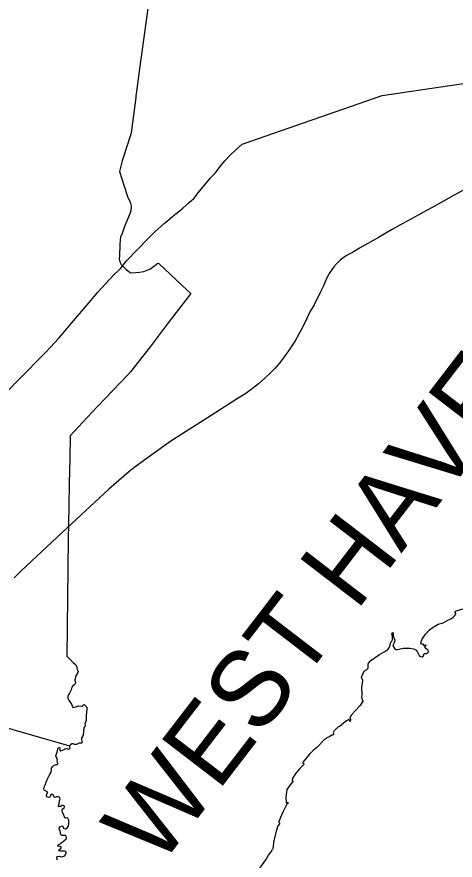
# Model space of a CAD drawing. Extents: x 0 to 2603, y -226 to 830.
# Drawn here: x 148.13 to 155.87, y 515.3 to 530.19 of the extents above; entities that cross this region are included whole.
import ezdxf

# ---------------------------------------------------------------- set-up
doc = ezdxf.new("R2010")
doc.units = 0
for name, color, linetype in [('CT_TSH_Map_Interstate_Roads', 7, 'Continuous'), ('CT_TSH_Map_Town_Limits', 7, 'Continuous'), ('CT_TSH_Map_Town_Text', 7, 'Continuous'), ('CT_TSH_Map_US_and_State_Routes', 7, 'Continuous')]:
    doc.layers.add(name, color=color, linetype=linetype)

msp = doc.modelspace()

# ---------------------------------------------------------------- linework, layer by layer
at = {"layer": 'CT_TSH_Map_Interstate_Roads'}
for p, q in [((155.849, 527.039), (155.475, 526.831)), ((155.217, 526.69), (155.022, 526.579)), ((154.747, 526.427), (154.512, 526.293)), ((154.512, 526.293), (154.182, 526.104)), ((153.724, 525.773), (153.657, 525.678)), ((153.657, 525.678), (153.605, 525.583)), ((149.753, 521.846), (149.506, 521.621)), ((148.66, 520.83), (148.482, 520.664)), ((148.482, 520.664), (148.199, 520.4)), ((148.199, 520.4), (148.081, 520.285))]:
    msp.add_line(p, q, dxfattribs=at)
for points in [[(156.789, 527.553), (156.703, 527.508), (156.56, 527.428), (156.136, 527.195), (155.849, 527.039)], [(155.475, 526.831), (155.364, 526.768), (155.217, 526.69)], [(155.022, 526.579), (154.889, 526.51), (154.747, 526.427)], [(154.182, 526.104), (154.056, 526.031), (153.983, 525.996), (153.931, 525.963), (153.838, 525.891), (153.781, 525.836), (153.724, 525.773)], [(153.605, 525.583), (153.545, 525.44), (153.487, 525.32)], [(153.487, 525.32), (153.422, 525.187), (153.39, 525.134)], [(153.39, 525.134), (153.376, 525.104), (153.298, 524.968), (153.249, 524.863), (153.18, 524.716), (153.079, 524.534)], [(153.079, 524.534), (153.041, 524.468), (152.926, 524.292), (152.85, 524.185)], [(152.85, 524.185), (152.765, 524.073), (152.683, 523.982), (152.603, 523.899), (152.515, 523.813), (152.394, 523.708)], [(152.394, 523.708), (152.261, 523.603), (152.154, 523.529), (152.035, 523.453), (151.561, 523.152), (150.848, 522.696), (150.495, 522.442)], [(150.495, 522.442), (150.194, 522.228), (150.104, 522.152), (149.753, 521.846)], [(149.506, 521.621), (149.096, 521.238), (148.66, 520.83)]]:
    msp.add_lwpolyline(points, dxfattribs=at)
at = {"layer": 'CT_TSH_Map_Town_Limits'}
for points in [[(150.486, 530.685), (150.296, 529.272), (150.233, 528.83), (150.23, 528.794), (150.23, 528.765), (150.15, 528.144), (150.132, 528.083), (150.014, 527.721), (149.988, 527.648), (149.942, 527.461), (150.022, 527.198), (150.08, 527.018), (150.13, 526.917), (150.15, 526.849), (150.143, 526.765), (150.125, 526.713), (150.028, 526.485), (149.987, 526.365), (149.96, 526.297), (149.952, 526.251), (149.949, 526.17), (149.942, 525.961), (149.938, 525.915), (149.946, 525.863), (149.971, 525.817), (150.057, 525.727), (150.131, 525.677), (150.162, 525.668), (150.297, 525.68), (150.372, 525.695), (150.489, 525.742), (150.619, 525.839), (150.633, 525.837), (151.047, 525.445), (151.2, 525.307), (150.802, 524.789), (150.481, 524.363), (150.135, 523.919), (150.086, 523.87), (149.554, 523.31), (149.289, 523.024), (149.071, 522.793), (149.064, 522.39), (149.05, 521.956), (149.045, 521.542), (149.036, 520.957), (149.009, 518.902), (149.122, 518.788), (149.172, 518.749), (149.185, 518.723), (149.195, 518.666), (149.214, 518.63), (149.205, 518.608), (149.166, 518.543), (149.164, 518.536), (149.158, 518.505), (149.15, 518.474), (149.166, 518.436), (149.163, 518.42), (149.15, 518.399), (149.126, 518.379), (149.102, 518.353), (149.088, 518.307), (149.057, 518.246), (149.038, 518.216), (149.03, 518.191), (149.031, 518.159), (149.053, 518.109), (149.096, 518.052), (149.117, 517.994), (149.171, 518.004), (149.226, 518.021), (149.274, 518.014), (149.295, 518.028), (149.312, 518.044), (149.324, 518.039), (149.349, 518.014), (149.364, 517.996), (149.367, 517.961), (149.354, 517.852), (149.352, 517.764), (149.331, 517.705), (149.334, 517.682), (149.342, 517.669), (149.318, 517.643), (149.312, 517.625), (149.299, 517.506), (149.269, 517.455), (149.273, 517.421), (149.283, 517.374), (149.274, 517.364), (149.261, 517.36), (149.224, 517.362), (149.181, 517.34), (149.149, 517.338), (149.121, 517.349), (149.1, 517.352), (149.078, 517.332)], [(155.509, 519.428), (155.57, 519.466), (155.656, 519.488), (155.74, 519.536), (155.79, 519.558), (155.832, 519.588), (155.861, 519.617)], [(155.861, 519.617), (155.878, 519.642), (155.87, 519.674), (155.88, 519.692), (155.923, 519.714), (156.053, 519.748), (156.101, 519.752)], [(154.746, 519.301), (154.77, 519.318)], [(154.77, 519.318), (154.772, 519.309), (154.776, 519.269), (154.787, 519.224), (154.802, 519.182), (154.796, 519.154), (154.765, 519.079)], [(155.266, 519.113), (155.261, 519.137), (155.288, 519.2), (155.344, 519.286), (155.415, 519.365), (155.477, 519.411), (155.509, 519.428)], [(154.746, 519.301), (154.754, 519.257), (154.758, 519.204), (154.751, 519.167)], [(154.457, 518.878), (154.53, 518.93), (154.616, 518.975), (154.686, 519.023)], [(154.686, 519.023), (154.711, 519.057), (154.728, 519.122)], [(154.751, 519.167), (154.728, 519.14), (154.723, 519.119)], [(154.817, 519.02), (154.771, 519.082)], [(154.817, 519.02), (154.846, 519.017), (154.952, 519.041), (155.068, 519.042), (155.139, 519.027), (155.18, 519.006), (155.199, 518.979), (155.234, 518.912), (155.258, 518.896), (155.288, 518.89), (155.31, 518.904), (155.31, 518.912)], [(155.272, 519.115), (155.291, 519.115), (155.314, 519.086), (155.345, 519.101), (155.355, 519.085), (155.327, 519.065), (155.338, 519.049)], [(155.31, 518.912), (155.322, 518.944), (155.365, 518.944), (155.387, 518.957), (155.396, 518.979), (155.39, 519.003), (155.374, 519.019), (155.359, 519.029)], [(155.338, 519.049), (155.359, 519.029)], [(154.418, 518.851), (154.457, 518.878)], [(154.215, 518.523), (154.231, 518.574), (154.266, 518.64), (154.319, 518.676), (154.33, 518.685), (154.335, 518.712), (154.331, 518.734), (154.33, 518.759), (154.336, 518.776)], [(154.336, 518.776), (154.374, 518.817), (154.394, 518.835), (154.418, 518.851)], [(154.226, 518.275), (154.221, 518.288), (154.218, 518.347), (154.238, 518.469), (154.215, 518.523)], [(154.176, 518.01), (154.182, 518.021), (154.203, 518.038), (154.239, 518.092), (154.248, 518.098), (154.235, 518.111), (154.225, 518.144), (154.221, 518.183), (154.228, 518.225), (154.226, 518.275)], [(154.035, 517.852), (154.041, 517.867), (154.176, 518.01)], [(154.022, 517.746), (154.026, 517.781), (154.013, 517.812), (154.019, 517.83), (154.03, 517.85), (154.035, 517.852)], [(147.746, 517.692), (149.06, 517.313)], [(153.801, 517.651), (153.827, 517.663), (153.865, 517.694)], [(153.988, 517.78), (153.952, 517.758), (153.865, 517.694)], [(154.022, 517.746), (153.988, 517.78)], [(153.582, 517.442), (153.611, 517.464), (153.647, 517.48), (153.685, 517.51), (153.71, 517.51), (153.723, 517.523), (153.719, 517.55), (153.736, 517.586), (153.801, 517.651)], [(153.423, 517.288), (153.572, 517.437), (153.582, 517.442)], [(148.897, 516.242), (148.867, 516.238), (148.862, 516.25), (148.874, 516.291), (148.879, 516.344), (148.892, 516.374), (148.888, 516.397), (148.87, 516.413), (148.837, 516.416), (148.799, 516.405), (148.786, 516.412), (148.777, 516.442), (148.767, 516.459), (148.744, 516.464), (148.731, 516.45), (148.72, 516.418), (148.701, 516.406), (148.656, 516.416), (148.65, 516.44), (148.667, 516.478), (148.673, 516.495), (148.611, 516.535), (148.608, 516.556), (148.618, 516.605), (148.629, 516.626), (148.667, 516.724), (148.704, 516.805), (148.736, 516.853), (148.74, 516.891), (148.74, 516.921), (148.768, 516.958), (148.789, 516.975), (148.817, 516.986), (148.847, 516.989), (148.853, 516.995), (148.852, 517.011), (148.839, 517.034), (148.839, 517.046), (148.848, 517.071), (148.834, 517.097), (148.82, 517.142), (148.829, 517.173), (148.842, 517.201), (148.855, 517.263), (148.873, 517.288), (148.89, 517.282), (148.89, 517.241), (148.908, 517.228), (148.963, 517.251), (148.976, 517.262), (149.003, 517.266), (149.041, 517.259), (149.06, 517.268), (149.069, 517.277), (149.06, 517.313)], [(149.078, 517.332), (149.06, 517.313)], [(153.423, 517.288), (153.369, 517.242), (153.297, 517.168), (153.235, 517.099), (153.187, 517.032), (153.181, 517.008)], [(153.2, 516.993), (153.125, 516.918), (153.058, 516.841), (152.996, 516.742), (152.988, 516.706), (152.988, 516.693)], [(153.2, 516.993), (153.181, 517.008)], [(153.005, 516.69), (152.952, 516.627), (152.898, 516.542), (152.889, 516.505), (152.881, 516.402), (152.887, 516.314), (152.888, 516.311)], [(153.005, 516.69), (152.988, 516.693)], [(148.848, 515.295), (148.838, 515.314), (148.833, 515.341), (148.836, 515.357), (148.848, 515.364), (148.876, 515.365), (148.914, 515.358), (148.96, 515.369), (148.976, 515.381), (148.999, 515.418), (148.998, 515.44), (148.989, 515.449), (148.979, 515.457), (148.895, 515.457), (148.873, 515.459), (148.869, 515.468), (148.872, 515.479), (148.9, 515.497), (148.914, 515.517), (148.911, 515.533), (148.882, 515.539), (148.854, 515.542), (148.85, 515.548), (148.863, 515.565), (148.919, 515.603), (148.998, 515.675), (149.006, 515.693), (149.002, 515.722), (148.983, 515.733), (148.923, 515.731), (148.903, 515.749), (148.901, 515.779), (148.892, 515.815), (148.88, 515.833), (148.878, 515.861), (148.899, 515.892), (148.928, 515.903), (148.935, 515.902), (148.955, 515.861), (148.982, 515.847), (148.992, 515.848), (149.02, 515.868), (149.041, 515.899), (149.048, 515.938), (149.046, 516.001), (149.028, 516.041), (149.015, 516.045), (148.985, 516.04), (148.976, 516.044), (148.961, 516.091), (148.935, 516.142), (148.929, 516.165), (148.929, 516.184), (148.942, 516.206), (148.964, 516.215), (148.971, 516.242), (148.966, 516.256), (148.947, 516.264), (148.93, 516.263), (148.897, 516.242)], [(152.924, 516.308), (152.897, 516.285), (152.831, 516.154), (152.779, 516.039), (152.756, 515.971), (152.757, 515.959)], [(152.924, 516.308), (152.888, 516.311)], [(152.775, 515.946), (152.737, 515.904), (152.711, 515.828), (152.669, 515.645), (152.647, 515.495), (152.642, 515.484)], [(152.775, 515.946), (152.757, 515.959)], [(151.782, 514.622), (151.834, 514.625), (151.933, 514.613), (151.968, 514.623), (151.996, 514.637), (152.061, 514.713), (152.16, 514.822), (152.179, 514.864), (152.195, 514.905), (152.204, 514.919), (152.227, 514.937), (152.303, 515.032), (152.332, 515.073), (152.435, 515.178), (152.524, 515.301), (152.571, 515.383), (152.617, 515.443), (152.642, 515.484)]]:
    msp.add_lwpolyline(points, dxfattribs=at)
at = {"layer": 'CT_TSH_Map_US_and_State_Routes'}
for p, q in [((151.061, 526.81), (151.174, 526.91)), ((149.095, 524.78), (149.441, 525.186)), ((148.947, 524.606), (149.095, 524.78)), ((148.607, 524.235), (148.635, 524.264)), ((148.177, 523.797), (148.285, 523.907))]:
    msp.add_line(p, q, dxfattribs=at)
for points in [[(152.109, 527.94), (154.582, 528.8), (158.161, 529.33), (162.146, 529.461)], [(151.802, 527.645), (151.897, 527.745), (151.997, 527.842), (152.109, 527.94)], [(151.55, 527.345), (151.634, 527.437), (151.717, 527.547), (151.802, 527.645)], [(151.174, 526.91), (151.261, 526.989), (151.327, 527.076), (151.448, 527.225), (151.55, 527.345)], [(150.879, 526.664), (150.938, 526.709), (151.061, 526.81)], [(149.918, 525.705), (149.964, 525.751), (150.065, 525.884), (150.26, 526.084), (150.45, 526.278), (150.571, 526.399), (150.728, 526.54), (150.787, 526.589), (150.879, 526.664)], [(149.762, 525.549), (149.859, 525.649), (149.918, 525.705)], [(149.441, 525.186), (149.561, 525.329), (149.762, 525.549)], [(148.635, 524.264), (148.725, 524.358), (148.864, 524.511), (148.947, 524.606)], [(148.285, 523.907), (148.505, 524.131), (148.607, 524.235)], [(147.379, 522.974), (147.526, 523.121), (147.618, 523.217), (147.721, 523.325), (147.943, 523.556), (148.177, 523.797)]]:
    msp.add_lwpolyline(points, dxfattribs=at)

# ---------------------------------------------------------------- texts
at = {"layer": 'CT_TSH_Map_Town_Text'}
msp.add_text('WEST HAVEN', height=1.35, rotation=52.4616, dxfattribs=at).set_placement((150.638, 515.143))

doc.saveas('drawing.dxf')
